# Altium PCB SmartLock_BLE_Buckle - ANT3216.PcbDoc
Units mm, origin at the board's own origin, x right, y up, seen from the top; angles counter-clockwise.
Board outline 30.4 x 18.6 mm, 2 copper layers (Top Layer, Bottom Layer); 38 components, 33 nets, 108 pads, 74 vias.
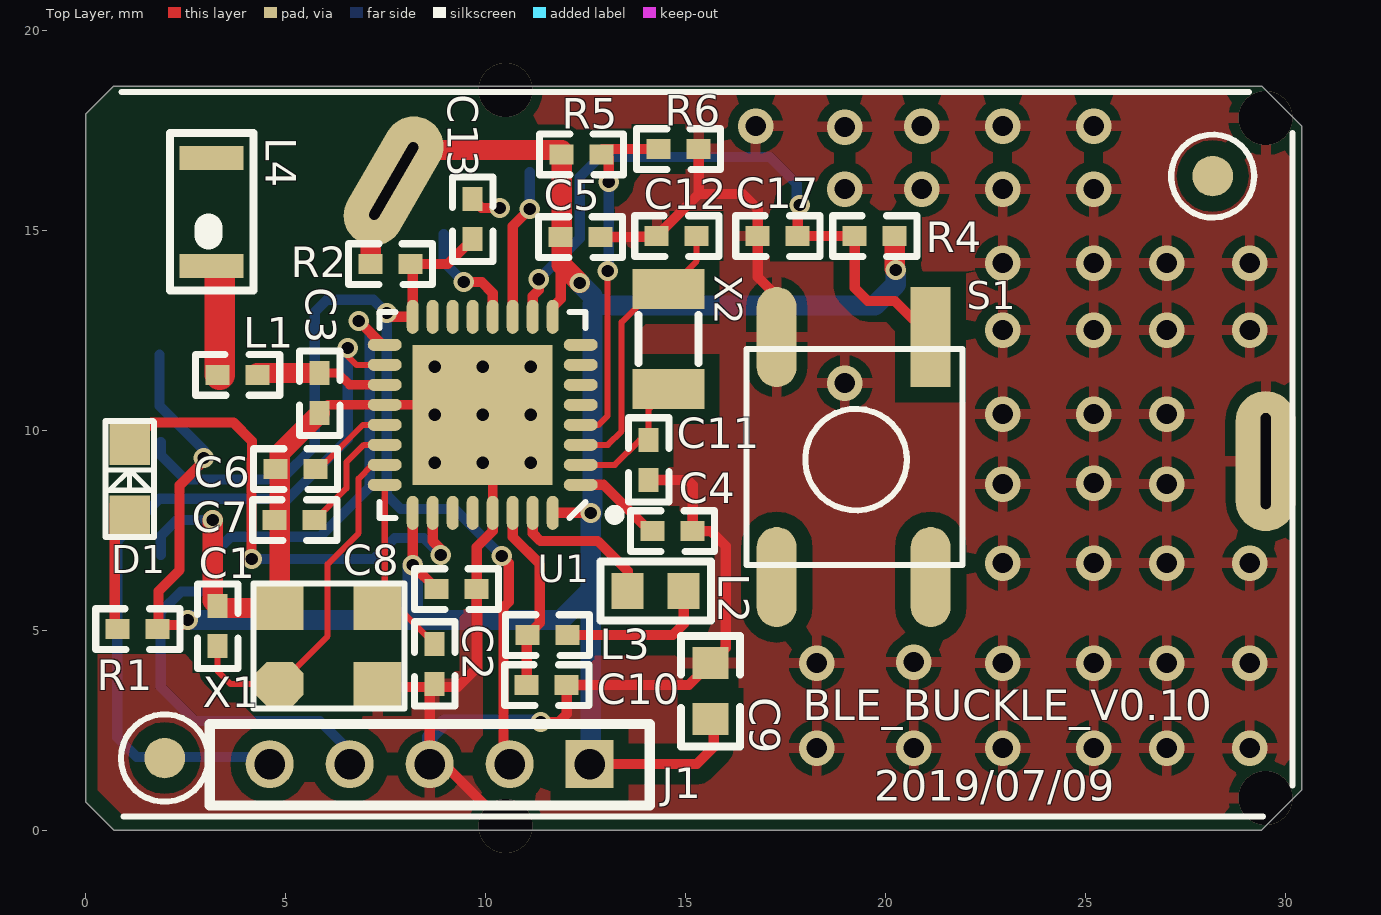
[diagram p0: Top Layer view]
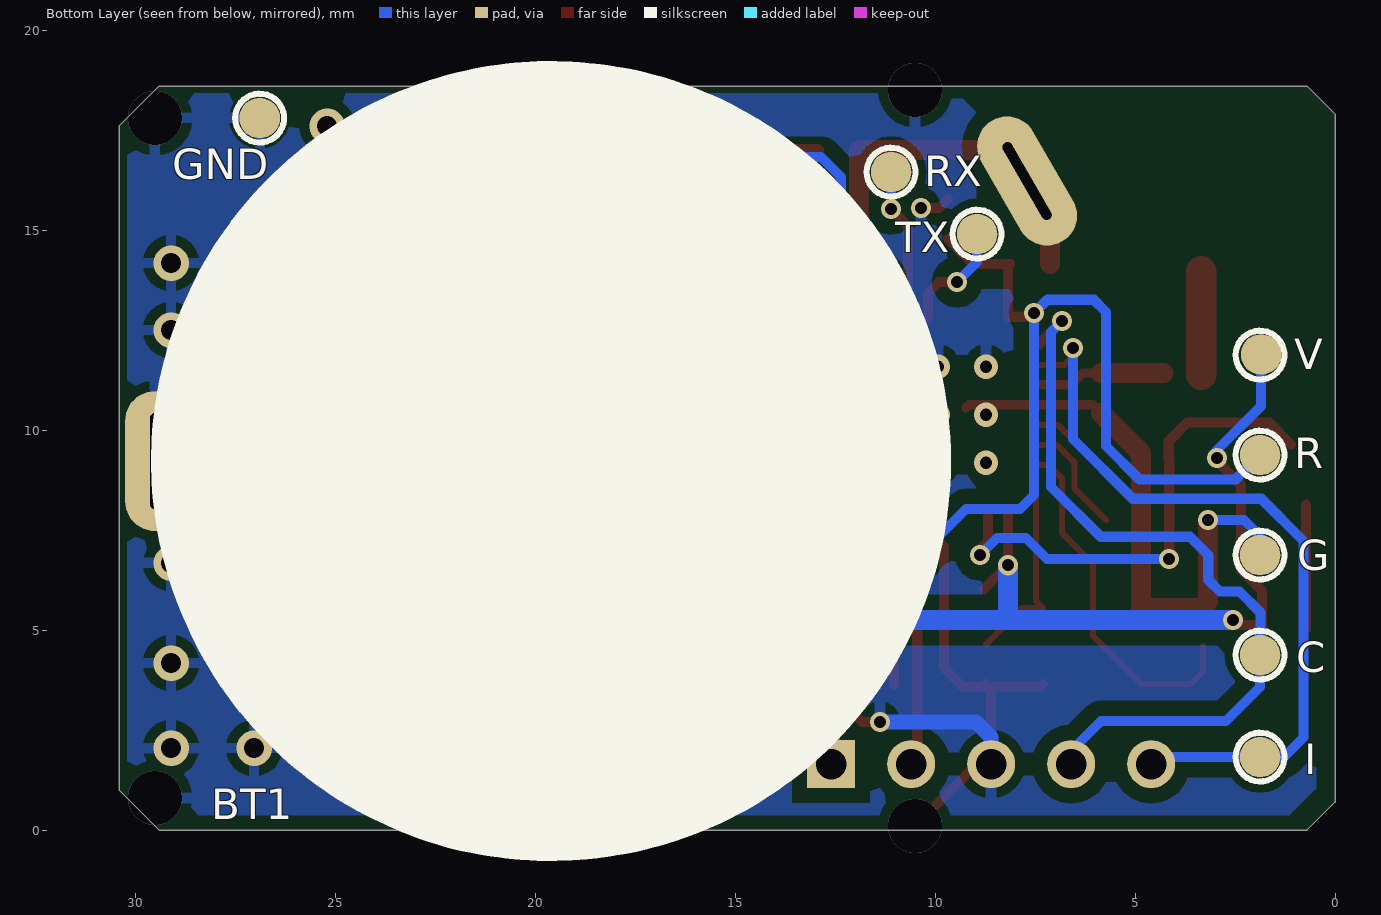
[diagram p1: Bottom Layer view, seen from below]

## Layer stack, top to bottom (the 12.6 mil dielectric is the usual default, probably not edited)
Top Solder: solder mask 0.0102, Solder Resist, Dk 3.5
Top Layer: signal copper 0.0356
Dielectric1: dielectric 0.32, FR-4, Dk 4.8
Bottom Layer: signal copper 0.0356
Bottom Solder: solder mask 0.0102, Solder Resist, Dk 3.5

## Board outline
0,0.7 0,17.9 0.7,18.6 29.4,18.6 30.4,17.6 30.4,1 29.4,0 0.7,0

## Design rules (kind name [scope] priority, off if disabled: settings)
Clearance polygen [InPolygon] p1: gap=0.381 ignorepadtopadclearanceinfootprint=FALSE except(0: Arc-Hole Track-Hole SMDPad-Hole THPad-Hole Via-Hole Fill-Hole Poly-Hole Region-Hole Text-Hole)
Clearance [All] p2: gap=0.152 ignorepadtopadclearanceinfootprint=FALSE except(0: Arc-Hole Track-Hole SMDPad-Hole THPad-Hole Via-Hole Fill-Hole Poly-Hole Region-Hole Text-Hole)
ComponentClearance [All] p1: gap=0 collisioncheckmode=3 verticalgap=0 showdistances=FALSE
HoleSize [All] p1: absolutevalues=TRUE maxlimit=254 minlimit=0.025 maxpercent=80.000 minpercent=20.000
HoleToHoleClearance [All] p1: gap=0 allowstackedmicrovias=TRUE
MinimumSolderMaskSliver [All] p1: minsoldermaskwidth=0
PolygonConnect [InNet('GND')] p1: connectstyle=Relief reliefconductorwidth=0.254 reliefentries=4 polygonreliefangle="90 Angle" airgapwidth=0.254
RoutingVias [All] p1: holewidth=0.711 width=1.27 viastyle="Through Hole" minholewidth=0.305 minwidth=0.61 maxholewidth=127 maxwidth=254
SilkToSilkClearance [All] p1: silktosilkclearance=0
SilkToSolderMaskClearance [IsPad] p1: minsilkscreentomaskgap=0 clearancetoexposedcopper=TRUE
SolderMaskExpansion [All] p1: expansion=0.102
Width VDD_NRF [InNet('VDD_NRF')] p1: maxlimit=0.508 minlimit=0.254 preferedwidth=0.254
Width GND [InNet('GND')] p2: maxlimit=1 minlimit=0.152 preferedwidth=0.5
Width [All] p3: maxlimit=0.762 minlimit=0.152 preferedwidth=0.152
24 further rules are at their usual default settings.

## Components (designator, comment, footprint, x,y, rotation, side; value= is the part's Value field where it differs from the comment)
BT1 "CR2032" BAT-CR2032 19.6,9.225 r0 bottom
C "TEST" "TP 40*40"#1 1.875,4.375 r0 bottom
C1 "12pF" 0402 3.3,4.6 r90 top
C2 "12pF" 0402 8.725,4.65 r270 top
C3 "0.8pF" 0402 5.85,10.425 r90 top
C4 "100nF" 0402 14.175,7.475 r0 top
C5 "100nF" 0402 11.875,14.825 r0 top
C6 "N.C." 0402 4.75,9.025 r0 top
C7 "100pF" 0402 5.725,7.75 r180 top
C8 "100nF" 0402 8.775,6.025 r0 top
C9 "4.7µF" 0603 15.625,2.775 r90 top
C10 "1.0µF" 0402 12.025,3.625 r180 top
C11 "NC/12pF" 0402 14.075,9.75 r270 top
C12 "NC/12pF" 0402 15.275,14.85 r180 top
C13 "0.1uF" 0402 9.675,14.775 r90 top
C17 "0.1uF" 0402 17.8,14.85 r180 top
D1 "LED-G" 0603_LED 1.1,8.75 r90 top (schematic designator LED1)
G "TEST" "TP 40*40"#1 1.875,6.875 r0 bottom
GND "TEST" "TP 40*40"#1 26.885,17.8 r270 bottom
I "TEST" "TP 40*40"#1 1.875,1.825 r0 bottom
J1 "NC/CON5" "HDR 5x1- 2MM" 12.6,1.65 r180 top
L1 "3.9nH" 0402 4.293,11.379 r180 top
L2 "10µH" "IND 0603" 14.95,5.975 r180 top
L3 "15nH" 0402 11.05,4.875 r0 top
L4 "" "3216 - ANT" 3.15,14.097 r90 top
R "TEST" "TP 40*40"#1 1.875,9.375 r0 bottom
R1 "330" 0402 1.8,5.025 r180 top
R2 "10K" 0402 7.125,14.15 r0 top
R4 "10K" 0402 20.225,14.85 r180 top
R5 "1M" 0402 11.9,16.891 r0 top
R6 "1M" 0402 14.325,17.025 r0 top
RX "TEST" "TP 40*40"#1 11.1,16.45 r270 bottom
S1 "SW DIP-2" SWQ-SW5.2*5.2*2.0-4 21.125,12.325 r270 top
TX "TEST" "TP 40*40"#1 8.95,14.9 r270 bottom
U1 "nRF52810-QCAA" Nordic_QFN50P500X500X90-33N 9.926,10.382 r180 top locked
V "TEST" "TP 40*40"#2 1.875,11.875 r0 bottom
X1 "32MHz" 3225 4.85,5.55 r0 top
X2 "NC/32.768kHz_" XTAL_3215 14.575,12.275 r90 top

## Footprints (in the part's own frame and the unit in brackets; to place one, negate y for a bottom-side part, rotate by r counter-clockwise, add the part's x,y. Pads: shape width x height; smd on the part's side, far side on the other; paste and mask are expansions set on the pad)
0402 [mm] "Chip Capacitor; Body 1.0 x 0.5 mm (LxW typ)"
  rect 0.6x0.5 smd: 1(0,0) 2(1,0)
  silkscreen extent -0.56,-0.51 1.55,0.51, body extent -0.05,-0.3 1.05,0.3, height 1.3
0603 [mm] "Chip Inductor, Body 0.6x0.3mm, IPC High Density"
  rect 0.8x0.9 smd: 1(0,0) 2(1.4,0)
  silkscreen extent -0.69,-0.74 2.08,0.74, body extent -0.18,-0.48 1.57,0.47, height 1.3
0603_LED [mil]
  rect 40x40 smd: 1(-35,0) 2(35,0)
  silkscreen extent -56,-24 58,24
"3216 - ANT" [mm] "ant  3216"
  rect 0.6x1.6 smd: 1(0,0) 2(2.7,0)
  silkscreen extent -0.61,-1.04 3.33,1.04
3225 [mm]
  oct 1.2x1.1 smd: 1(0,-1.9)
  rect 1.2x1.1 smd: 2(2.45,-1.9) 3(2.45,0) 4(0,0)
  silkscreen extent -0.66,-2.51 3.12,0.61
BAT-CR2032 [mm]
  oval 3.5x1.5 hole 0.25 slot 2.2 at 120 deg rot 120 mask+0: 1(-11.9,-7)
  oval 1.5x3.5 hole 0.25 slot 2.4 at 90 deg mask+0: 2(9.9,0)
  silkscreen extent -5,-5 5,5
"HDR 5x1- 2MM" [mm]
  rect 1.2x1.2 hole 0.762: 1(0,0)
  round 1.2 hole 0.762: 2(2,0) 3(4,0) 4(6,0) 5(8,0)
  silkscreen extent -1.5,-1 9.5,1.03
"IND 0603" [mm] "Chip Inductor, Body 0.6x0.3mm, IPC High Density"
  rect 0.8x0.9 smd: 1(0,0) 2(1.4,0)
  silkscreen extent -0.69,-0.74 2.08,0.74, body extent -0.18,-0.48 1.57,0.47, height 1.3
Nordic_QFN50P500X500X90-33N [mm] "QFN32 5x5x0.85mm, 0.5mm pitch - Medium Density"
  oval 0.85x0.3 smd mask+0.076: 1(-2.45,1.75) 2(-2.45,1.25) 3(-2.45,0.75) 4(-2.45,0.25) 5(-2.45,-0.25) 6(-2.45,-0.75) 7(-2.45,-1.25) 8(-2.45,-1.75) 17(2.45,-1.75) 18(2.45,-1.25) 19(2.45,-0.75) 20(2.45,-0.25) 21(2.45,0.25) 22(2.45,0.75) 23(2.45,1.25) 24(2.45,1.75)
  oval 0.3x0.85 smd mask+0.076: 9(-1.75,-2.45) 10(-1.25,-2.45) 11(-0.75,-2.45) 12(-0.25,-2.45) 13(0.25,-2.45) 14(0.75,-2.45) 15(1.25,-2.45) 16(1.75,-2.45) 25(1.75,2.45) 26(1.25,2.45) 27(0.75,2.45) 28(0.25,2.45) 29(-0.25,2.45) 30(-0.75,2.45) 31(-1.25,2.45) 32(-1.75,2.45)
  rect 3.5x3.5 smd: 33(0,0)
  silkscreen extent -3.43,-2.57 2.57,2.62, body extent -2.5,-2.5 2.5,2.5, height 0.9
SWQ-SW5.2*5.2*2.0-4 [mm]
  rect 2.5x1 smd mask+0: 1(0,0)
  oval 2.5x1 smd mask+0: 2(0,-3.85) 3(6,-3.85) 4(6,0)
  silkscreen extent 0.3,-4.6 5.7,0.8, body extent 0.78,-4.15 5.35,0.42, height 3.8
"TP 40*40"#1 [mil] "实心圆形测试点内直径40mil"
  round 40 smd: 1(0,0)
  silkscreen extent -24,-24 24,24
"TP 40*40"#2 [mil] "实心圆形测试点内直径40mil"
  round 40 smd: 1(-1.06,-0.67)
  silkscreen extent -24,-24 24,24
XTAL_3215 [mm] "XTAL SMD 3.2 x 1.5 mm"
  rect 1x1.8 smd: 1(-1.25,0) 2(1.25,0)
  silkscreen extent -0.6,-0.75 0.6,0.75, body extent -1.6,-0.75 1.6,0.75, height 0.81

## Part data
BT1: library part Battery, "纽扣电池座"
C1 C2 C11 C12: library part C0402-12p, "Capacitor, NP0, ±2%"
C3: library part C0402-0.8p, "Capacitor, NP0, ±5%"
C4 C5 C8: library part C0402-100n, "Capacitor, X7R, ±10%"
C6: library part C0402-N.C., "Not mounted"
C7: library part C0402-100p, "Capacitor, NP0, ±5%"
C9: library part C0603-4μ7, "Capacitor, X5R, ±10%"
C10: library part C0603-1μ0, "Capacitor, X7R, ±10%"
C13 C17: library part C-XX-XXX, "贴片电容"
D1: "LED绿色"
J1: library part CON5, "单排排针，间距2毫米"
L1 L4: library part L0402-3n9, "High frequency chip inductor ±5%"
L2: library part L0603-10μ, "Chip inductor, IDC,min = 50 mA, ±20%"
L3: library part L0402-15n, "High frequency chip inductor ±10%"
R1 R2 R4: library part R-XXXJ, "贴片电阻"
R5 R6: library part R, "1%精度"
S1: "DIP Switch, 2 Position, SPST"
U1: "Multi-protocol Bluetooth Low Energy, ANT and 2.4GHz proprietary system-on-chip"
X1: library part XTAL_SMD2016_32MHz_8pF_General, "贴片式无源晶振"
X2: library part XTAL_SMD3215_32.768kHz_9pF_General, "贴片式无源晶振"

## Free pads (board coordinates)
  round 1.016 smd: 2(1.975,1.8) 3(28.175,16.35)

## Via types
v1: diameter 0.889, hole 0.508, Top Layer to Bottom Layer, 40 vias
v2: diameter 0.508, hole 0.305, Top Layer to Bottom Layer, 21 vias
v3: diameter 0.61, hole 0.305, Top Layer to Bottom Layer, tented bottom, 9 vias
v4: diameter 1.35, hole 1.35, Top Layer to Bottom Layer, tented both sides, 4 vias

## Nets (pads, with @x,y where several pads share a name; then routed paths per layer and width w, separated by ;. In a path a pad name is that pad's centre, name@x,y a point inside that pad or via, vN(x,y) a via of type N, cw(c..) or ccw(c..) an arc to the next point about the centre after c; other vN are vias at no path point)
ANT: L4.2
DEC1: C4.1 U1.1 | length 2.3
  Top Layer w0.254: U1.1 12.943,8.632 14.1,7.475 C4.1
DEC2: C6.2 U1.21 | length 2.2
  Top Layer w0.152: C6.2 5.826,9.025 6.933,10.132 U1.21
DEC3: C7.1 U1.22 | length 2.9
  Top Layer w0.152: C7.1 6.517,8.542 6.517,9.195 6.954,9.632 U1.22
DEC4: C10.2 L3.1 U1.30 | length 4.7
  Top Layer w0.254: U1.30 10.676,7.329 11.35,6.654 11.35,5.175 L3.1 11.025,4.85 C10.2
GND: BT1.2 C1.2 C2.2 C3.1 C4.2 C5.2 C6.1 C7.2 C8.2 C9.2 C10.1 C11.2 C12.2 C13.2 C17.2 G.1 GND.1 J1.3 R6.2 S1.2 U1.20 U1.29 U1.33 X1.2 X1.4 | length 53.5
  Top Layer w0.229: C3.1 6.057,10.632 U1.20 9.151,10.632 U1.33@9.226,10.557 ; v3(9.926,10.382) 10.176,10.132 U1.29
  Top Layer w0.254: X1.2 7.375,3.575 C2.2@8.65,3.575 ; C2.2 C2.2@8.65,3.575 ; C13.2 9.9,15.55 v2(10.35,15.55) ; U1.29 10.176,7.476 9.775,7.075 C8.2 9.775,4.05 9.3,3.575 C2.2@8.65,3.575 ; v4(10.5,0.1) 8.95,1.65 J1.3 8.6,3.525 C2.2@8.65,3.575 ; v2(11.375,2.7) 11.825,2.7 12.025,2.9 C10.1 15.075,3.625 C9.2 16,4.55 16,7.1 15.625,7.475 C4.2 15.175,8.625 15.05,8.75 C11.2 ; C5.2 14.25,14.825 C12.2 15.325,15.9 ; R6.2 15.325,15.9 ; S1.2 17.275,13.35 16.8,13.825 C17.2 16.8,15.525 16.425,15.9 15.325,15.9
  Top Layer w0.508: v2(3.175,7.75) 3.175,5.725 C1.2 3.35,5.55 X1.4 4.85,9.425 C3.1
  Bottom Layer w0.254: G.1 1.875,7.35 2.275,7.75 v2(3.175,7.75)
  Bottom Layer w0.381: J1.3 8.6,2.325 8.975,2.7 v2(11.375,2.7)
  other v1: 18.275,2.05 20.7,2.05 22.925,2.05 25.2,2.05 27.025,2.05 29.1,2.05 18.275,4.175 22.925,4.175 25.2,4.175 27.025,4.175 29.1,4.175 20.7,4.2 22.925,6.675 25.2,6.675 27.025,6.675 29.1,6.675 22.925,8.65 27.025,8.65 25.2,8.675 22.925,10.4 25.2,10.4 27.025,10.4 18.975,11.175 22.925,12.5 25.2,12.5 27.025,12.5 29.1,12.5 22.925,14.175 25.2,14.175 27.025,14.175 29.1,14.175 18.975,16.025 20.9,16.025 22.925,16.025 25.2,16.025 18.975,17.575 16.75,17.6 20.9,17.6 22.925,17.6 25.2,17.6
  other v3: 8.726,9.182 9.926,9.182 11.126,9.182 8.726,10.382 11.126,10.382 8.726,11.582 9.926,11.582 11.126,11.582
  other v4: 29.5,0.8 29.5,17.8 10.5,18.5
LED1: D1.2 U1.26 | length 12.7
  Top Layer w0.254: D1.2 1.653,10.192 3.688,10.192 4.159,9.721 4.159,9.28 4.146,9.267 4.146,6.779 v2(4.15,6.775) ; U1.26 8.676,7.224 8.875,7.025 v2(8.875,6.875)
  Bottom Layer w0.254: v2(4.15,6.775) 7.2,6.775 7.725,7.3 8.45,7.3 v2(8.875,6.875)
NetC3_2: C3.2 L1.1 U1.19 | length 3.3
  Top Layer w0.229: C3.2 6.304,11.425 6.597,11.132 U1.19
  Top Layer w0.508: L1.1@4.293,11.425 C3.2
NetD1_1: D1.1 R1.2 | length 3.1
  Top Layer w0.254: R1.2@0.725,5.025 D1.1@0.725,8.136
NetL1_2: L1.2 L4.1 | length 2.6
  Top Layer w0.762: L1.2@3.35,11.379 L4.1@3.35,13.973
NetL2_1: L2.1 L3.2 | length 3.8
  Top Layer w0.254: L3.2 14.675,4.875 14.95,5.15 L2.1
NetL2_2: L2.2 U1.31 | length 3.8
  Top Layer w0.254: U1.31 11.176,7.419 11.367,7.227 12.798,7.227 13.55,6.475 L2.2
P0.00/XL1: C11.1 U1.2 X2.1 | length 3.5
  Top Layer w0.152: U1.2 13.232,9.132 C11.1@13.85,9.75 ; C11.1 C11.1@13.85,9.75 ; X2.1 14.075,10.525 14.075,9.975 C11.1@13.85,9.75
P0.01/XL2: C12.1 U1.3 X2.2 | length 7
  Top Layer w0.152: U1.3 13.057,9.632 13.4,9.975 13.4,12.7 14.225,13.525 X2.2 15.275,14.225 C12.1
P0.04/AIN2: R5.2 R6.1 U1.4 | length 9.2
  Top Layer w0.152: U1.4 12.824,10.132 13.05,10.358 v2(13.05,13.975)
  Top Layer w0.254: v2(13.075,16.2) 13.075,16.825 12.9,17 12.925,17.025 R6.1
  Bottom Layer w0.152: v2@13.05,13.82 v2(13.05,13.975) ; v2@13.095,16.2 13.095,16.32 v2@13.1,16.325
  Bottom Layer w0.254: v2(13.05,13.975) 13.075,14 v2(13.075,16.2)
P0.05/AIN3: U1.5
P0.06: U1.6
P0.09: U1.7
P0.10: U1.8
P0.12: C17.1 R4.2 S1.1 U1.10 | length 16.4
  Top Layer w0.254: U1.10 11.176,13.35 11.326,13.5 v2(11.326,13.769) ; v2(17.85,15.625) 17.8,15.575 C17.1 R4.2 19.225,13.55 19.55,13.225 20.225,13.225 S1.1
  Bottom Layer w0.254: v2(11.326,13.769) 12.35,14.793 12.35,16.325 12.85,16.825 17.1,16.825 17.775,16.15 v2@17.775,15.6
P0.14: RX.1 U1.11 | length 3.8
  Top Layer w0.254: U1.11 10.676,15.101 v2(11.1,15.525) v2@11.125,15.55
  Bottom Layer w0.254: v2(11.1,15.525) RX.1
P0.15: TX.1 U1.12 | length 2.8
  Top Layer w0.254: v2(9.45,13.7) 9.9,13.7 10.176,13.424 U1.12
  Bottom Layer w0.254: TX.1 8.95,14.2 v2(9.45,13.7)
P0.16: U1.13
P0.18: U1.14
P0.20: U1.15
P0.21: C13.1 J1.2 R2.2 R.1 U1.16 | length 27.5
  Top Layer w0.254: v2(7.525,12.925) 7.618,12.832 U1.16 8.176,14.099 R2.2 9.05,14.15 C13.1 ; v2(10.4,6.85) 10.575,6.675 10.575,5.7 10.446,5.571 10.446,1.804 J1.2
  Bottom Layer w0.254: R.1@1.875,9.7 R.1 2.483,8.767 4.892,8.767 5.725,9.6 5.725,12.95 6.033,13.258 7.192,13.258 v2(7.525,12.925) 7.525,8.375 7.875,8.025 9.225,8.025 v2(10.4,6.85)
P0.28/AIN4: U1.27
P0.30/AIN6: U1.28
SWDCLK: C.1 J1.4 U1.17 | length 19.6
  Top Layer w0.254: v2(6.825,12.725) 7.418,12.132 U1.17
  Bottom Layer w0.254: J1.4 6.6,1.975 5.85,2.725 2.725,2.725 1.875,3.575 C.1 1.867,4.383 1.867,5.442 2.387,5.962 2.875,5.962 3.169,6.256 3.169,6.875 3.627,7.333 5.858,7.333 7.1,8.575 7.1,12.45 v2(6.825,12.725)
SWDIO: I.1 J1.5 U1.18 | length 19.3
  Top Layer w0.152: v2(6.55,12.05) 6.55,11.85 6.768,11.632 U1.18
  Bottom Layer w0.254: J1.5 4.425,1.825 I.1 1.275,1.825 0.787,2.312 0.787,7.225 1.846,8.283 5.058,8.283 6.55,9.775 v2(6.55,12.05)
VDD_NRF: BT1.1 C5.1 C8.1 C9.1 J1.1 R1.1 R2.1 R4.1 R5.1 U1.9 U1.25 U1.32 V.1 | length 60.4
  Top Layer w0.254: v2(2.55,5.25) 2.424,5.124 1.824,5.124 1.824,5.975 2.349,6.501 2.349,8.624 v2@2.875,9.15 ; U1.25 v2(8.176,6.624) C8.1 ; U1.32 12.618,7.932 v2(12.625,7.925) ; U1.9 11.676,13.076 11.875,13.275 C5.1 C5.1@11.9,14.85 ; J1.1 15.275,1.65 15.7,2.075 15.7,2.7 C9.1 ; v2@20.225,14.025 v2(20.25,14)
  Top Layer w0.508: R2.1 7.125,15.825 8.3,17 11.9,17 11.9,14.85 11.9,14.128 12.35,13.678 v2(12.35,13.675) ; v2@20.225,14.025 R4.1
  Bottom Layer w0.254: V.1 1.848,10.602 2.95,9.5 v2(2.95,9.3) ; J1.1 J1.1@12.625,1.675
  Bottom Layer w0.508: v2(2.55,5.25) 8.175,5.25 11.875,5.25 12.625,6 ; 8.176,5.251 v2(8.176,6.624) ; v2(12.35,13.675) 12.669,13.356 ; J1.1@12.625,1.675 12.625,6 ; v2(12.625,7.925) 12.625,6 ; v2@12.669,7.925 12.669,13.15 ; 12.975,13.15 13.01,13.115 19.725,13.115 20.25,13.64 v2(20.25,14)
XC1: C1.1 U1.23 X1.1 | length 9.1
  Top Layer w0.152: C1.1 3.3,3.975 3.625,3.65 X1.1 6.05,4.85 6.05,6.65 6.822,7.422 6.822,8.789 7.165,9.132 U1.23
XC2: C2.1 U1.24 X1.3 | length 5
  Top Layer w0.152: U1.24 7.476,5.726 X1.3 7.825,5.55 C2.1
pads on no net: S1.3 S1.4

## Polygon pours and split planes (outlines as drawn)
GND on Bottom Layer "GND Layer-No Net" (solid, remove dead copper, pour order 10): 30.275,17.5 30.15,17.5 29.225,18.425 9.45,18.425 9.275,18.25 8.975,17.95 8.975,13.525 6.95,13.525 6.95,7.5 6.375,6.925 0.45,6.925 0.475,6.9 0.475,1.025 0.5,1.025 1.15,0.375 29.075,0.375 29.5,0.8 30,1.3 30.025,1.3 30.025,1.45 30.2,1.625 30.2,17.425 30.25,17.475
GND on Top Layer "GND Layer-No Net" (solid, remove dead copper, pour order 12): 28.925,0.375 30.175,1.625 30.175,1.65 30.175,17.425 29.2,18.4 28.85,18.4 9.425,18.4 9.15,18.125 9.1,18.075 9.1,13.25 7.45,13.25 7.325,13.375 7.45,13.25 7.45,6.5 0.375,6.5 0.3,6.425 0.3,1 0.725,0.575 0.9,0.4 2.95,0.4

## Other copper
Top Layer:
  pour cut-out: 4.211,11.932 6.954,11.932 6.954,9.62 4.211,9.62
  pour cut-out: -0.015,18.605 6.462,18.605 6.462,9.537 -0.015,9.537
Bottom Layer:
  pour cut-out: 0,18.6 6.452,18.6 6.452,9.507 0,9.507

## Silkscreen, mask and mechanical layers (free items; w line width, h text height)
Top Overlay:
  circle w0.152: c28.175,16.35 r1.04
  circle w0.152: c1.975,1.8 r1.093
  lines w0.152: 0.9,18.451 29.083,18.451 ; 0.951,0.341 29.426,0.341 ; 30.175,1.118 30.175,17.425
  text "BLE_BUCKLE_V0.10" at 17.932,2.743 h0.76
  text "2019/07/09" at 19.71,0.737 h0.76
Mechanical 2:
  lines w0.152: 0,17.9 0,0.7 0.7,0 11.2,0 29.4,0 30.4,1 30.4,17.6 29.4,18.6 0.7,18.6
